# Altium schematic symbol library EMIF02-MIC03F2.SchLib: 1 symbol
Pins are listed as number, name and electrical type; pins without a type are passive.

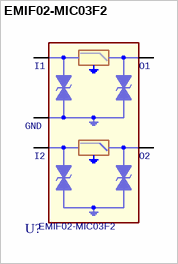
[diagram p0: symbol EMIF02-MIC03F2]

## EMIF02-MIC03F2
designator U?
footprint ST_CSP05N43P3X3_107X147X65
pins: A1 I1, A3 I2, B2 GND, C1 O1, C3 O2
